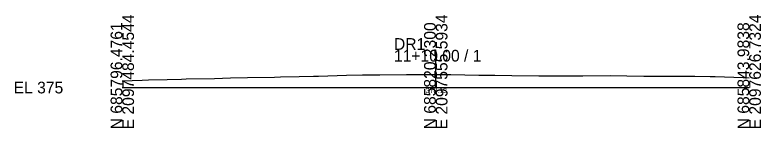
# Model space of a CAD drawing. Extents: x -26 to 1303, y -10 to 2517.
# Drawn here: x 1124.3 to 1302.8, y -9.7 to 17.4 of the extents above; entities that cross this region are included whole.
import ezdxf

# ---------------------------------------------------------------- set-up
doc = ezdxf.new("R2010")
doc.units = 0
for name, color, linetype in [('Default', 7, 'Continuous'), ('Exist Cross Section Cell', 7, 'Continuous'), ('Exist XS Center Line Elevation Label', 7, 'Continuous'), ('Exist XS Ground Line', 7, 'Continuous')]:
    doc.layers.add(name, color=color, linetype=linetype)

msp = doc.modelspace()

# ---------------------------------------------------------------- linework, layer by layer
at = {"layer": 'Exist Cross Section Cell'}
for p, q in [((1225, 0), (1225, 9.02)), ((1150, 0), (1225, 0)), ((1225, 0), (1300, 0))]:
    msp.add_line(p, q, dxfattribs=at)
at = {"layer": 'Exist XS Ground Line'}
msp.add_lwpolyline([(1150, 1.6), (1154.77, 1.77), (1156.25, 1.82), (1160.71, 1.94), (1164.16, 2.04), (1165.31, 2.05), (1172.06, 2.19), (1175.85, 2.35), (1179.97, 2.42), (1186.4, 2.51), (1187.87, 2.54), (1192.29, 2.63), (1195.78, 2.7), (1196.94, 2.72), (1203.68, 2.93), (1207.48, 3.04), (1211.59, 3.05), (1218.03, 3.14), (1223.86, 3.14), (1225, 3.13), (1227.39, 3.12), (1228.57, 3.1), (1235.3, 2.98), (1239.12, 2.95), (1243.2, 2.91), (1249.66, 2.83), (1251.11, 2.82), (1255.44, 2.8), (1259.01, 2.81), (1260.2, 2.8), (1266.92, 2.85), (1270.75, 2.83), (1274.82, 2.73), (1281.29, 2.74), (1282.73, 2.72), (1287.02, 2.69), (1290.63, 2.64), (1291.84, 2.61), (1298.54, 2.38), (1300, 2.35)], dxfattribs=at)

# ---------------------------------------------------------------- texts
at = {"layer": 'Default'}
msp.add_text('-', height=0.0001, dxfattribs=at).set_placement((1150, 0))
at = {"layer": 'Exist Cross Section Cell'}
for s, p in [('E 2097484.4544', (1152.8, -10)), ('E 2097555.5934', (1227.8, -10)), ('E 2097626.7324', (1302.8, -10)), ('N 685796.4761', (1150, -10)), ('N 685820.2300', (1225, -10)), ('N 685843.9838', (1300, -10))]:
    msp.add_text(s, height=2.8, rotation=90, dxfattribs=at).set_placement(p)
for s, p in [('DR1', (1215, 9.02)), ('11+10.00 / 1', (1215, 6.22)), ('EL 375', (1124, -1.4))]:
    msp.add_text(s, height=2.8, dxfattribs=at).set_placement(p)
at = {"layer": 'Exist XS Center Line Elevation Label'}
msp.add_text('378.13', height=1.2, dxfattribs=at).set_placement((1222.61, -1.32))
msp.add_text('378.13', height=1.2, dxfattribs=at).set_placement((1222.61, -1.32))

doc.saveas('drawing.dxf')
